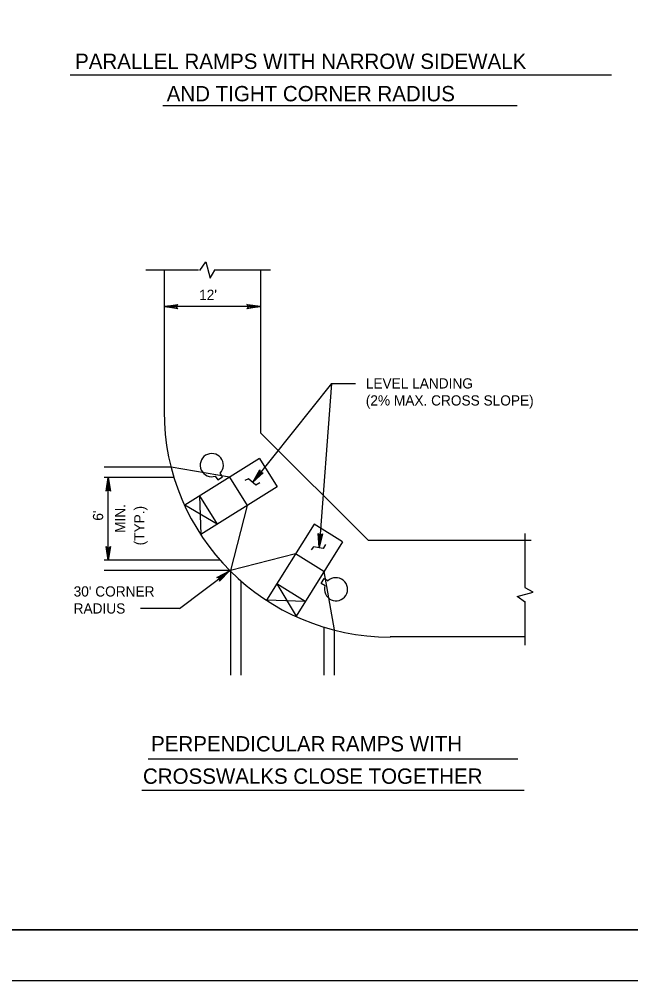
# Model space of a CAD drawing. Extents: x -344 to 940, y 22 to 1233.
# Drawn here: x 84.3 to 263.8, y 22.2 to 304.6 of the extents above; entities that cross this region are included whole.
import ezdxf

# ---------------------------------------------------------------- set-up
doc = ezdxf.new("R2010")
doc.units = 0
for name, color, linetype in [('1', 7, 'Continuous'), ('2', 7, 'Continuous'), ('PLT-BNDY', 7, 'Continuous')]:
    doc.layers.add(name, color=color, linetype=linetype)

msp = doc.modelspace()

# ---------------------------------------------------------------- linework, layer by layer
at = {"layer": '1'}
for p, q in [((861.86, 37.17), (75.86, 37.17)), ((75.86, 37.17), (661.86, 37.17))]:
    msp.add_line(p, q, dxfattribs=at)
at = {"layer": '2'}
for p, q in [((258.09, 288.11), (99.21, 288.11)), ((230.47, 279.11), (126.42, 279.11)), ((136.91, 230.84), (121.44, 230.84)), ((126.79, 230.84), (126.79, 189.46)), ((158.07, 230.84), (141.54, 230.84)), ((155.12, 230.84), (155.12, 183.11)), ((155.12, 220.17), (126.79, 220.17)), ((175.96, 197.61), (152.83, 168.62)), ((175.96, 197.61), (172.35, 149.4)), ((175.96, 197.61), (182.95, 197.61)), ((155.12, 183.11), (186.76, 151.47)), ((154.77, 175.52), (132.92, 161.86)), ((154.77, 175.52), (159.96, 167.21)), ((128.85, 173.06), (109.25, 173.06)), ((146.02, 170.05), (128.85, 173.06)), ((129.71, 169.99), (109.25, 169.99)), ((110.43, 145.69), (110.43, 169.99)), ((141.84, 170.38), (142.53, 169.28)), ((142.53, 169.28), (143.94, 170.15)), ((143.94, 170.15), (143.25, 171.26)), ((146.02, 170.05), (151.21, 161.74)), ((159.96, 167.21), (137.57, 153.22)), ((137.23, 164.55), (142.41, 156.25)), ((137.23, 164.55), (137.57, 153.22)), ((142.41, 156.25), (132.92, 161.86)), ((151.21, 161.74), (146.31, 142.62)), ((170.87, 156.31), (156.87, 133.91)), ((179.17, 151.12), (170.87, 156.31)), ((232.79, 137.68), (232.79, 153.49)), ((179.17, 151.12), (165.52, 129.27)), ((234.49, 151.47), (186.76, 151.47)), ((165.4, 147.56), (146.27, 142.66)), ((173.7, 142.37), (165.4, 147.56)), ((143.29, 145.69), (109.25, 145.69)), ((146.31, 142.62), (109.25, 142.62)), ((131.32, 131.51), (145.97, 142.54)), ((146.27, 142.66), (146.27, 111.88)), ((173.7, 142.37), (176.72, 125.2)), ((149.34, 139.63), (149.34, 111.88)), ((168.21, 133.57), (159.9, 138.76)), ((159.9, 138.76), (165.52, 129.27)), ((172.93, 138.88), (173.81, 140.28)), ((174.03, 138.19), (172.93, 138.88)), ((173.81, 140.28), (174.91, 139.59)), ((168.21, 133.57), (156.87, 133.91)), ((232.79, 120.76), (232.79, 133.43)), ((131.32, 131.51), (119.87, 131.51)), ((173.65, 126.06), (173.65, 111.88)), ((176.72, 125.2), (176.72, 111.88)), ((232.79, 123.14), (193.12, 123.14)), ((122.13, 87.39), (230.57, 87.39)), ((120.29, 78.19), (232.51, 78.19))]:
    msp.add_line(p, q, dxfattribs=at)
for points in [[(137.34, 230.81), (139.03, 233.29), (140.29, 228.55), (141.65, 230.92)], [(130.65, 219.68), (130.51, 219.96), (126.79, 220.17), (130.65, 219.68), (130.85, 219.52), (126.79, 220.17), (130.5, 220.35), (130.64, 220.63), (126.79, 220.17), (130.85, 220.81), (130.64, 220.63)], [(151.26, 220.65), (151.4, 220.37), (155.12, 220.17), (151.26, 220.65), (151.06, 220.82), (155.12, 220.17), (151.41, 219.99), (151.27, 219.71), (155.12, 220.17), (151.06, 219.52), (151.27, 219.71)], [(109.95, 166.13), (110.23, 166.28), (110.43, 169.99), (109.95, 166.13), (109.78, 165.94), (110.43, 169.99), (110.62, 166.28), (110.89, 166.15), (110.43, 169.99), (111.08, 165.94), (110.89, 166.15)], [(154.91, 168.41), (153.74, 167.74), (151.53, 169.57), (150.48, 169.12)], [(155.62, 171.33), (155.31, 171.4), (152.83, 168.62), (155.62, 171.33), (155.87, 171.38), (152.83, 168.62), (155, 171.64), (154.87, 171.91), (152.83, 168.62), (154.86, 172.19), (154.87, 171.91)], [(173.12, 153.22), (172.84, 153.09), (172.35, 149.4), (173.12, 153.22), (173.31, 153.4), (172.35, 149.4), (172.45, 153.12), (172.18, 153.27), (172.35, 149.4), (172.01, 153.5), (172.18, 153.27)], [(110.92, 149.55), (110.64, 149.4), (110.43, 145.69), (110.92, 149.55), (111.09, 149.74), (110.43, 145.69), (110.25, 149.4), (109.97, 149.53), (110.43, 145.69), (109.79, 149.74), (109.97, 149.53)], [(174.13, 150.28), (173.45, 149.12), (170.62, 149.6), (169.94, 148.69)], [(142.59, 140.61), (142.88, 140.47), (145.97, 142.54), (142.59, 140.61), (142.33, 140.62), (145.97, 142.54), (143.11, 140.16), (143.17, 139.86), (145.97, 142.54), (143.11, 139.58), (143.17, 139.86)], [(232.87, 133.31), (230.39, 135), (235.13, 136.26), (232.76, 137.62)]]:
    msp.add_lwpolyline(points, dxfattribs=at)
for centre, radius, start, end in [((193.12, 189.46), 66.33, 180, 270), ((140.8, 173.61), 3.4, 316.1014, 287.8986), ((177.26, 137.15), 3.4, 162.1014, 133.8986)]:
    msp.add_arc(centre, radius, start, end, dxfattribs=at)
at = {"layer": 'PLT-BNDY'}
msp.add_lwpolyline([(35.86, 616.17), (876.86, 616.17), (876.86, 22.17), (35.86, 22.17)], close=True, dxfattribs=at)

# ---------------------------------------------------------------- texts
at = {"layer": '2'}
for s, height, p in [('PARALLEL RAMPS WITH NARROW SIDEWALK', 4.5, (100.68, 289.97)), ('AND TIGHT CORNER RADIUS', 4.5, (127.57, 280.47)), ("12'", 3, (137.09, 222.13)), ('LEVEL LANDING', 3, (186, 196.12)), ('(2% MAX. CROSS SLOPE)', 3, (186, 191.12)), ("30' CORNER", 3, (100.26, 135.02)), ('RADIUS', 3, (100.26, 130.02)), ('PERPENDICULAR RAMPS WITH', 4.5, (122.99, 89.52)), ('CROSSWALKS CLOSE TOGETHER', 4.5, (120.61, 80.02))]:
    msp.add_text(s, height=height, dxfattribs=at).set_placement(p)
for s, p in [('MIN.', (115.4, 153.71)), ('(TYP.)', (121.04, 150.05)), ("6'", (108.92, 157.3))]:
    msp.add_text(s, height=3, rotation=90, dxfattribs=at).set_placement(p)

doc.saveas('drawing.dxf')
